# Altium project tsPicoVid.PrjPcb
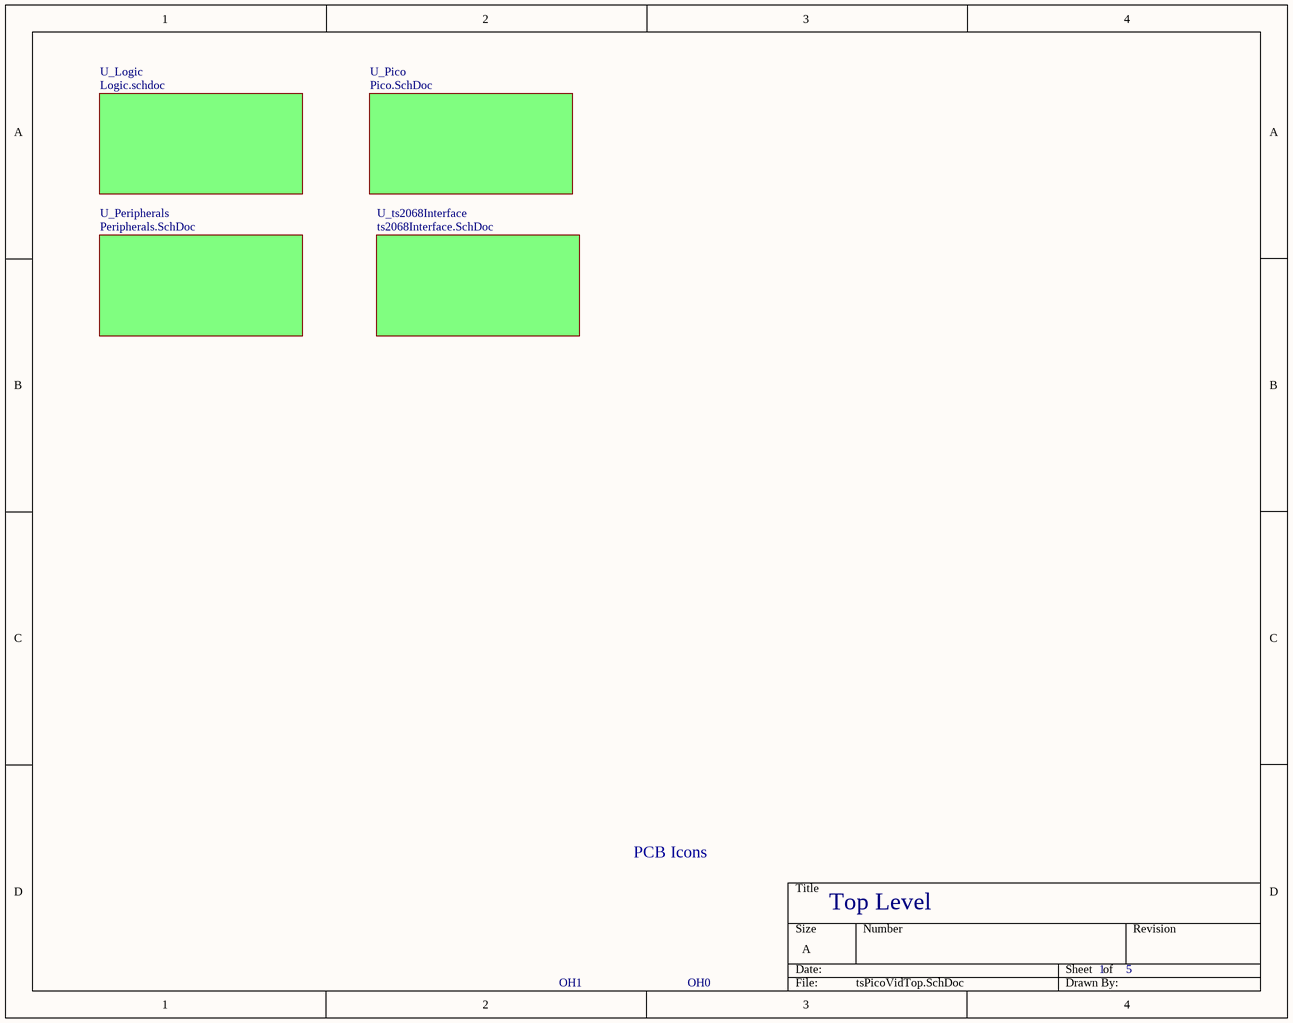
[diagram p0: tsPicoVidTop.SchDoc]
5 sheets, 47 parts. Net scope: global (net labels, ports and power ports of the same name join across sheets).
Sheets:
  tsPicoVidTop.SchDoc
    U_Logic = Logic.schdoc
    U_Pico = Pico.SchDoc
    U_ts2068Interface = ts2068Interface.SchDoc
    U_Peripherals = Peripherals.SchDoc

## Sheet tsPicoVidTop.SchDoc
size A; SheetNumber: 1; SheetTotal: 5

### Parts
OH0  OPENHW_PCB  [OpenHW]  (value not drawn)
OH1  OPENHW_SCH  (value not drawn)

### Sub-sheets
U_Logic = Logic.schdoc: no entries
U_Peripherals = Peripherals.SchDoc: no entries
U_Pico = Pico.SchDoc: no entries
U_ts2068Interface = ts2068Interface.SchDoc: no entries

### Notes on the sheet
- PCB Icons
- Top Level

## Sheet Logic.schdoc
size A; SheetNumber: 3; SheetTotal: 5
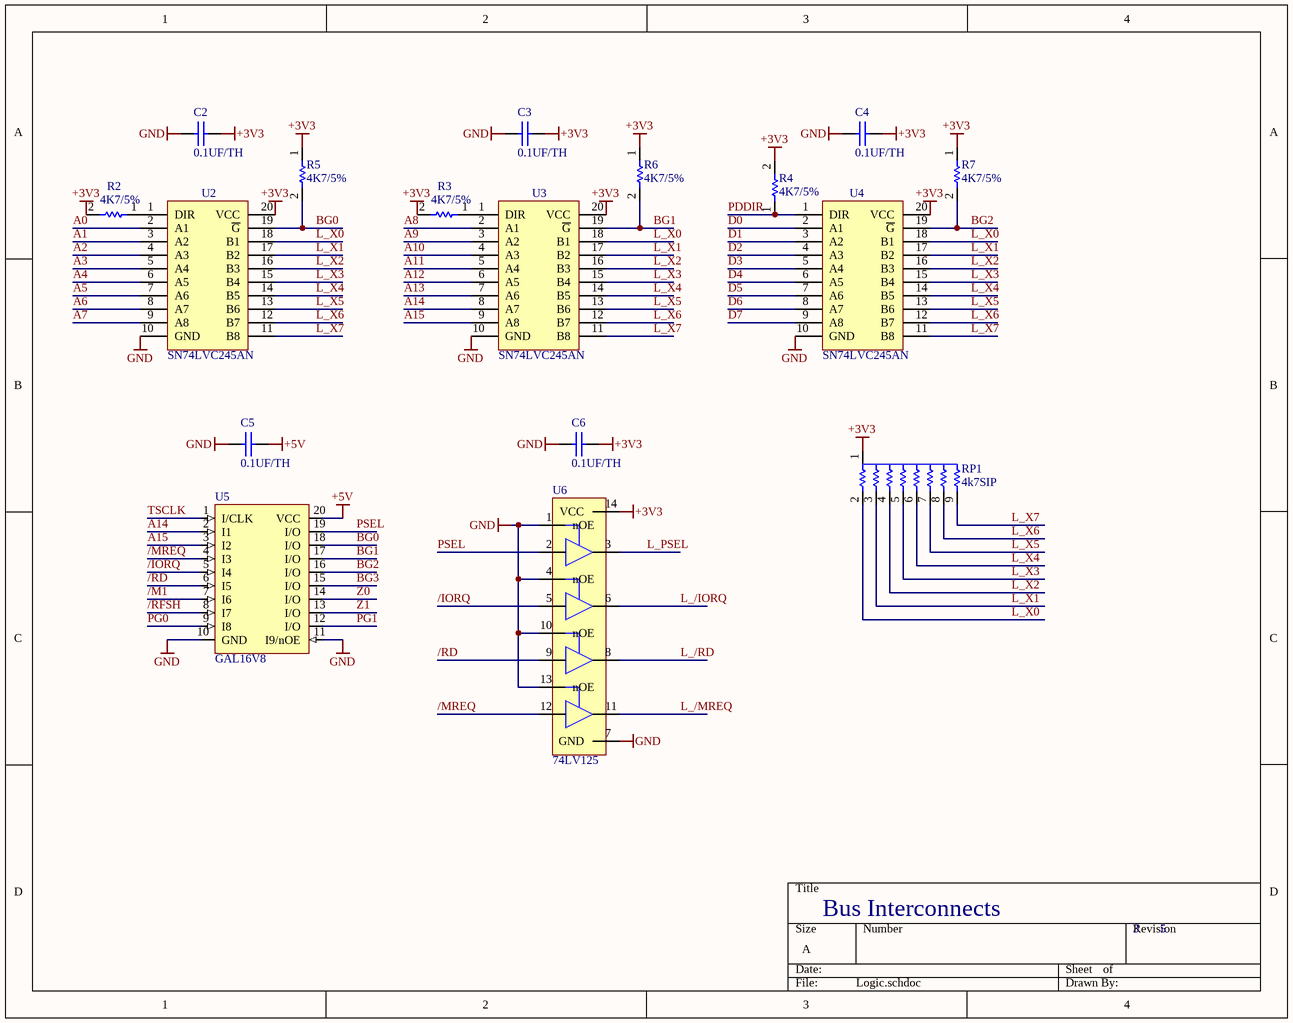
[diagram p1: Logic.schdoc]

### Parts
C2  0.1UF/TH  [CAPH5]
C3  0.1UF/TH  [CAPH5]
C4  0.1UF/TH  [CAPH5]
C5  0.1UF/TH  [CAPH5]
C6  0.1UF/TH  [CAPH5]
R2  4K7/5%  [CF18]
R3  4K7/5%  [CF18]
R4  4K7/5%  [CF18]
R5  4K7/5%  [CF18]
R6  4K7/5%  [CF18]
R7  4K7/5%  [CF18]
RP1  4k7SIP  [SIP9]
U2  SN74LVC245AN  [DIP20]
U3  SN74LVC245AN  [DIP20]
U4  SN74LVC245AN  [DIP20]
U5  GAL16V8  [DIP20]
U6  74LV125  [dip14]

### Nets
+3V3: C2.2 C3.2 C4.2 C6.2 R2.2 R3.2 R4.2 R5.1 R6.1 R7.1 RP1.1 U2.20(VCC) U3.20(VCC) U4.20(VCC) U6.14(VCC)
+5V: C5.2 U5.20(VCC)
GND: C2.1 C3.1 C4.1 C5.1 C6.1 U2.10(GND) U3.10(GND) U4.10(GND) U5.10(GND) U5.11(I9/nOE) U6.1(nOE) U6.4(nOE) U6.7(GND) U6.10(nOE) U6.13(nOE)
/IORQ: U5.5(I4) U6.5
/M1: U5.7(I6)
/MREQ: U5.4(I3) U6.12
/RD: U5.6(I5) U6.9
/RFSH: U5.8(I7)
A0: U2.2(A1)
A1: U2.3(A2)
A2: U2.4(A3)
A3: U2.5(A4)
A4: U2.6(A5)
A5: U2.7(A6)
A6: U2.8(A7)
A7: U2.9(A8)
A8: U3.2(A1)
A9: U3.3(A2)
A10: U3.4(A3)
A11: U3.5(A4)
A12: U3.6(A5)
A13: U3.7(A6)
A14: U3.8(A7) U5.2(I1)
A15: U3.9(A8) U5.3(I2)
BG0: R5.2 U2.19(~{G}) U5.18(I/O)
BG1: R6.2 U3.19(~{G}) U5.17(I/O)
BG2: R7.2 U4.19(~{G}) U5.16(I/O)
BG3: U5.15(I/O)
D0: U4.2(A1)
D1: U4.3(A2)
D2: U4.4(A3)
D3: U4.5(A4)
D4: U4.6(A5)
D5: U4.7(A6)
D6: U4.8(A7)
D7: U4.9(A8)
L_/IORQ: U6.6
L_/MREQ: U6.11
L_/RD: U6.8
L_PSEL: U6.3
L_X0: RP1.2 U2.18(B1) U3.18(B1) U4.18(B1)
L_X1: RP1.3 U2.17(B2) U3.17(B2) U4.17(B2)
L_X2: RP1.4 U2.16(B3) U3.16(B3) U4.16(B3)
L_X3: RP1.5 U2.15(B4) U3.15(B4) U4.15(B4)
L_X4: RP1.6 U2.14(B5) U3.14(B5) U4.14(B5)
L_X5: RP1.7 U2.13(B6) U3.13(B6) U4.13(B6)
L_X6: RP1.8 U2.12(B7) U3.12(B7) U4.12(B7)
L_X7: RP1.9 U2.11(B8) U3.11(B8) U4.11(B8)
PDDIR: R4.1 U4.1(DIR)
PG0: U5.9(I8)
PG1: U5.12(I/O)
PSEL: U5.19(I/O) U6.2
TSCLK: U5.1(I/CLK)
Z0: U5.14(I/O)
Z1: U5.13(I/O)
NetR2_1: R2.1 U2.1(DIR)
NetR3_1: R3.1 U3.1(DIR)

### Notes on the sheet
- Bus Interconnects

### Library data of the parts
C2-C6 = 0.1UF/TH: 0.1 µF ±10% 50V Ceramic Capacitor X7R Radial; MFG: Vishay; MFG PN: K104K10X7RF5UH5; DK PN: BC2665CT-ND
R2-R7 = 4K7/5%: RES 4.7K OHM 5% 1/8W AXIAL; MFG PN: CF18JT4K70; DK PN: CF18JT4K70CT-ND; MFG: Stackpole
RP1 = 4k7SIP: 4.7k Ohm ±2% 200mW Power Per Element Bussed Resistor Network/Array ±100ppm/°C 9-SIP; MFG: Bournes; MFG PN: 4609X-101-472LF; DK PN: 4609X-101-472LF-ND
U2-U4 = SN74LVC245AN: Transceiver, Non-Inverting 1 Element 8 Bit per Element 3-State Output 20-PDIP; MFG: TI; DK PN: 296-8503-5-ND
U5 = GAL16V8: GAL16V8 Programmable Logic Device (PLD) IC 8 Macrocells 20-PDIP; MFG: Microchip; MFG PN: ATF16V8C-7PU
U6 = 74LV125: Buffer, Non-Inverting 4 Element 1 Bit per Element 3-State Output 14-SOIC; MFG: TI; MFG PN: SN74LV125AN; DK PN: 296-34037-5-ND

## Sheet Pico.SchDoc: Mass Storage
size A; SheetNumber: 4; SheetTotal: 7
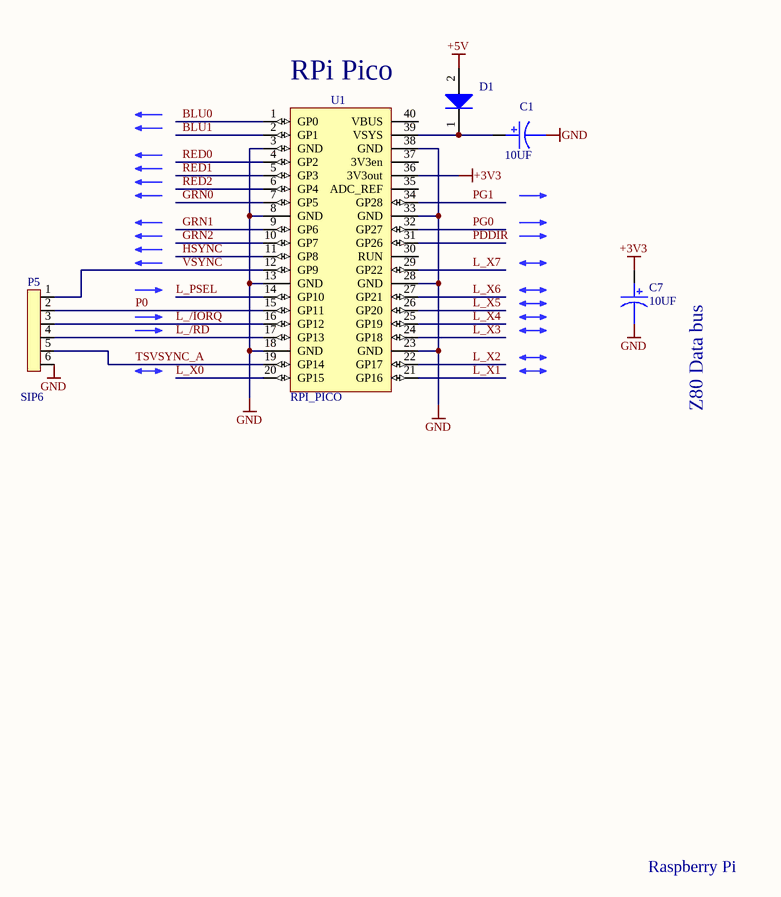
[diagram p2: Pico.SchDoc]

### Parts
C1  10UF  [CAP10EL]
C7  10UF  [CAP10EL]
D1  SB260_R2_00001  [DO-15]  (value not drawn)
P5  SIP6  [SIP6]
U1  RPI_PICO  [RPIPICO]

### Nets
+3V3: C7.1 U1.36(3V3out)
+5V: D1.2(A)
GND: C1.2 C7.2 P5.6 U1.3(GND) U1.8(GND) U1.13(GND) U1.18(GND) U1.23(GND) U1.28(GND) U1.33(GND) U1.38(GND)
BLU0: U1.1(GP0)
BLU1: U1.2(GP1)
GRN0: U1.7(GP5)
GRN1: U1.9(GP6)
GRN2: U1.10(GP7)
HSYNC: U1.11(GP8)
L_/IORQ: P5.3 U1.16(GP12)
L_/RD: P5.4 U1.17(GP13)
L_PSEL: U1.14(GP10)
L_X0: U1.20(GP15)
L_X1: U1.21(GP16)
L_X2: U1.22(GP17)
L_X3: U1.24(GP18)
L_X4: U1.25(GP19)
L_X5: U1.26(GP20)
L_X6: U1.27(GP21)
L_X7: U1.29(GP22)
P0: P5.2 U1.15(GP11)
PDDIR: U1.31(GP26)
PG0: U1.32(GP27)
PG1: U1.34(GP28)
RED0: U1.4(GP2)
RED1: U1.5(GP3)
RED2: U1.6(GP4)
TSVSYNC_A: P5.5 U1.19(GP14)
VSYNC: P5.1 U1.12(GP9)
NetC1_1: C1.1 D1.1 U1.39(VSYS)

Not connected (* = marked no-connect by the designer): U1 30(RUN) 35(ADC_REF) 37(3V3en) 40(VBUS)

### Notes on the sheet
- RPi Pico
- (near C7) Z80 Data bus
- Raspberry Pi

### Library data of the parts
C1 C7 = 10UF: CAP ALUM 10UF 20% 16V RADIAL; MFG: Panasonic; MFG PN: ECE-A1CKA100; DK PN: P807-ND
D1 = SB260_R2_00001: DIODE SCHOTTKY 60V 2A DO15; DK PN: 3757-SB260_R2_00001CT-ND; MFG: Panjit
U1 = RPI_PICO: RASPBERRY PI PICO RP2040 BOARD; MFG PN: SC0915; DK PN: 2648-SC0915CT-ND

## Sheet ts2068Interface.SchDoc
size A; SheetNumber: 2; SheetTotal: 5
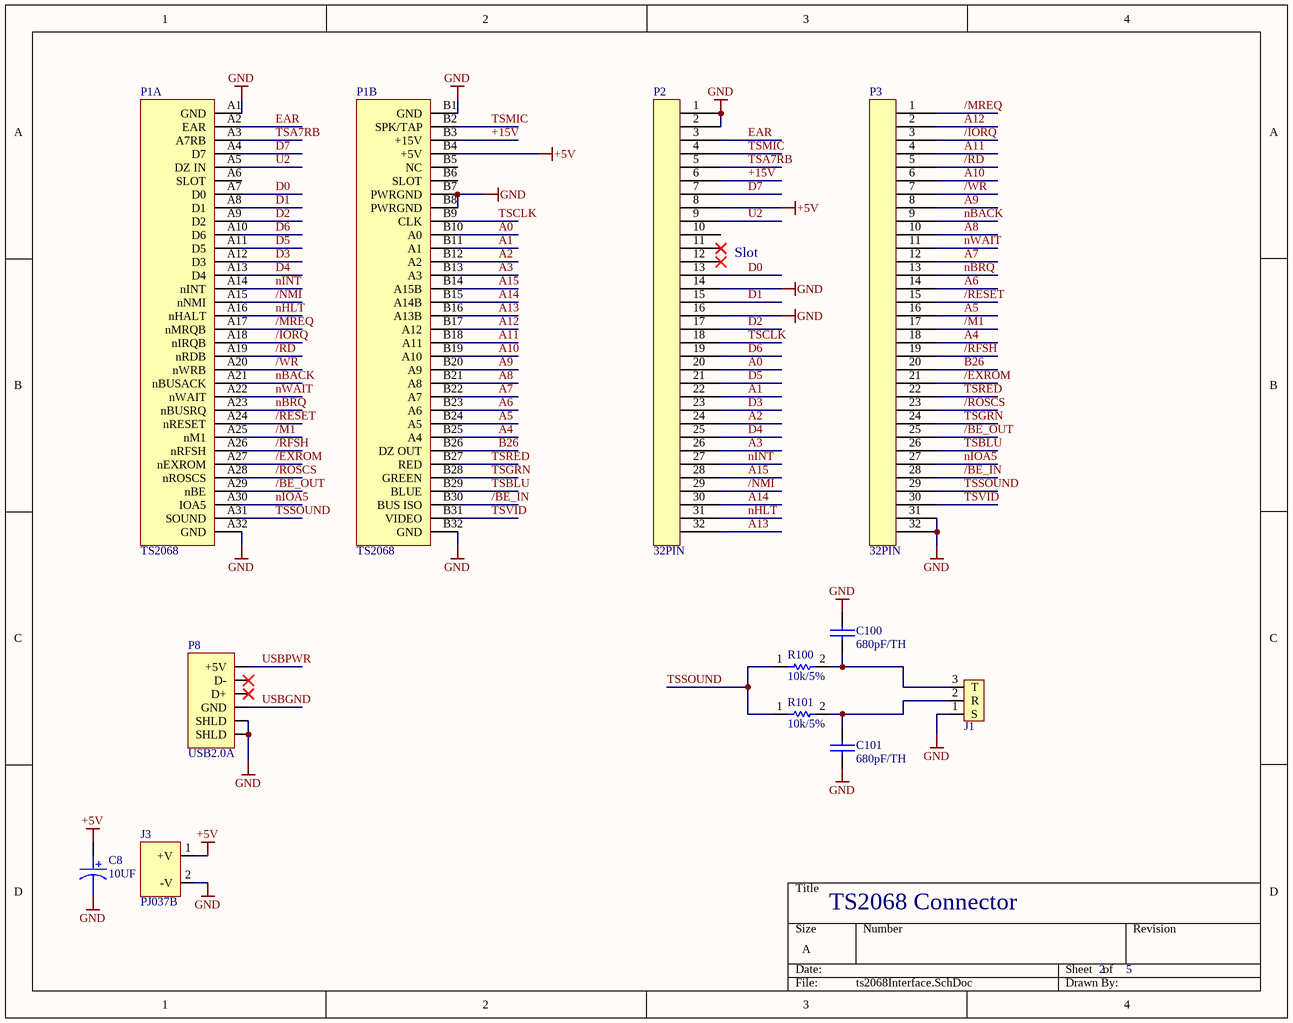
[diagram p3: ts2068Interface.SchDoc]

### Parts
C8  10UF  [CAP10EL]
C100  680pF/TH  [WIMIA_BOX2.7X4.5]
C101  680pF/TH  [WIMIA_BOX2.7X4.5]
J1  STX-3000  [STX-3000]  (value not drawn)
J3  PJ037B  [PJ037B]
P1  TS2068  [TS2068A]  (parts A,B of 2)
P2  32PIN  [IDC32]
P3  32PIN  [IDC32]
P8  USB2.0A  [USBA_AU-Y1005]
R100  10k/5%  [CF18]
R101  10k/5%  [CF18]

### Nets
+5V: C8.1 J3.1(+V) P1.B4(+5V) P2.8
GND: C8.2 C100.1 C101.2 J1.1(S) J3.2(-V) P1.A1(GND) P1.A32(GND) P1.B1(GND) P1.B7(PWRGND) P1.B8(PWRGND) P1.B32(GND) P2.1 P2.2 P2.14 P2.16 P3.31 P3.32 P8.5(SHLD) P8.6(SHLD)
+15V: P1.B3(+15V) P2.6
/BE_IN: P1.B30(BUS_ISO) P3.28
/BE_OUT: P1.A29(nBE) P3.25
/EXROM: P1.A27(nEXROM) P3.21
/IORQ: P1.A18(nIRQB) P3.3
/M1: P1.A25(nM1) P3.17
/MREQ: P1.A17(nMRQB) P3.1
/NMI: P1.A15(nNMI) P2.29
/RD: P1.A19(nRDB) P3.5
/RESET: P1.A24(nRESET) P3.15
/RFSH: P1.A26(nRFSH) P3.19
/ROSCS: P1.A28(nROSCS) P3.23
/WR: P1.A20(nWRB) P3.7
A0: P1.B10(A0) P2.20
A1: P1.B11(A1) P2.22
A2: P1.B12(A2) P2.24
A3: P1.B13(A3) P2.26
A4: P1.B25(A4) P3.18
A5: P1.B24(A5) P3.16
A6: P1.B23(A6) P3.14
A7: P1.B22(A7) P3.12
A8: P1.B21(A8) P3.10
A9: P1.B20(A9) P3.8
A10: P1.B19(A10) P3.6
A11: P1.B18(A11) P3.4
A12: P1.B17(A12) P3.2
A13: P1.B16(A13B) P2.32
A14: P1.B15(A14B) P2.30
A15: P1.B14(A15B) P2.28
B26: P1.B26(DZ_OUT) P3.20
D0: P1.A7(D0) P2.13
D1: P1.A8(D1) P2.15
D2: P1.A9(D2) P2.17
D3: P1.A12(D3) P2.23
D4: P1.A13(D4) P2.25
D5: P1.A11(D5) P2.21
D6: P1.A10(D6) P2.19
D7: P1.A4(D7) P2.7
EAR: P1.A2(EAR) P2.3
nBACK: P1.A21(nBUSACK) P3.9
nBRQ: P1.A23(nBUSRQ) P3.13
nHLT: P1.A16(nHALT) P2.31
nINT: P1.A14(nINT) P2.27
nIOA5: P1.A30(IOA5) P3.27
nWAIT: P1.A22(nWAIT) P3.11
TSA7RB: P1.A3(A7RB) P2.5
TSBLU: P1.B29(BLUE) P3.26
TSCLK: P1.B9(CLK) P2.18
TSGRN: P1.B28(GREEN) P3.24
TSMIC: P1.B2(SPK/TAP) P2.4
TSRED: P1.B27(RED) P3.22
TSSOUND: P1.A31(SOUND) P3.29 R100.1 R101.1
TSVID: P1.B31(VIDEO) P3.30
U2: P1.A5(DZ_IN) P2.9
USBGND: P8.4(GND)
USBPWR: P8.1(+5V)
NetC100_2: C100.2 J1.3(T) R100.2
NetC101_1: C101.1 J1.2(R) R101.2

Not connected (* = marked no-connect by the designer): P1 A6(SLOT) B5(NC) B6(SLOT); P2 10 11* 12*; P8 2(D-)* 3(D+)*

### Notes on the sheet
- Slot
- TS2068 Connector

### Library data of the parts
C8 = 10UF: as C1 on sheet Pico
C100 C101 = 680pF/TH: CAP FILM 680PF 10% 100VDC RAD; MFG: WIMA; MFG PN: FKP2D006801D00KSSD; DK PN: 1928-1238-ND
J1 = STX-3000: 3.50mm (0.141", 1/8", Mini Plug) - Headphone Phone Jack Stereo (3 Conductor, TRS) Connector Kinked Pin; DK PN: 2092-STX-3000-ND; MFG: Kycon, Inc.
J3 = PJ037B: Power Barrel Connector Jack 2.50mm ID (0.098"), 5.50mm OD (0.217") Through Hole, Right Angle; MFG PN: PJ-037B; DK PN: CP-037B-ND; MFG: CUI
P8 = USB2.0A: USB-A (USB TYPE-A) USB 2.0 Receptacle Connector 4 Position Through Hole, Right Angle; MFG: Adam Tech; MFG PN: USB-A-S-RA; DK PN: 2057-USB-A-S-RA-ND
R100 R101 = 10k/5%: RES 10K OHM 5% 1/8W AXIAL; MFG PN: CF18JT10K0; DK PN: CF18JT10K0CT-ND; MFG: Stackpole

## Sheet Peripherals.SchDoc
size A; SheetNumber: 4; SheetTotal: 5
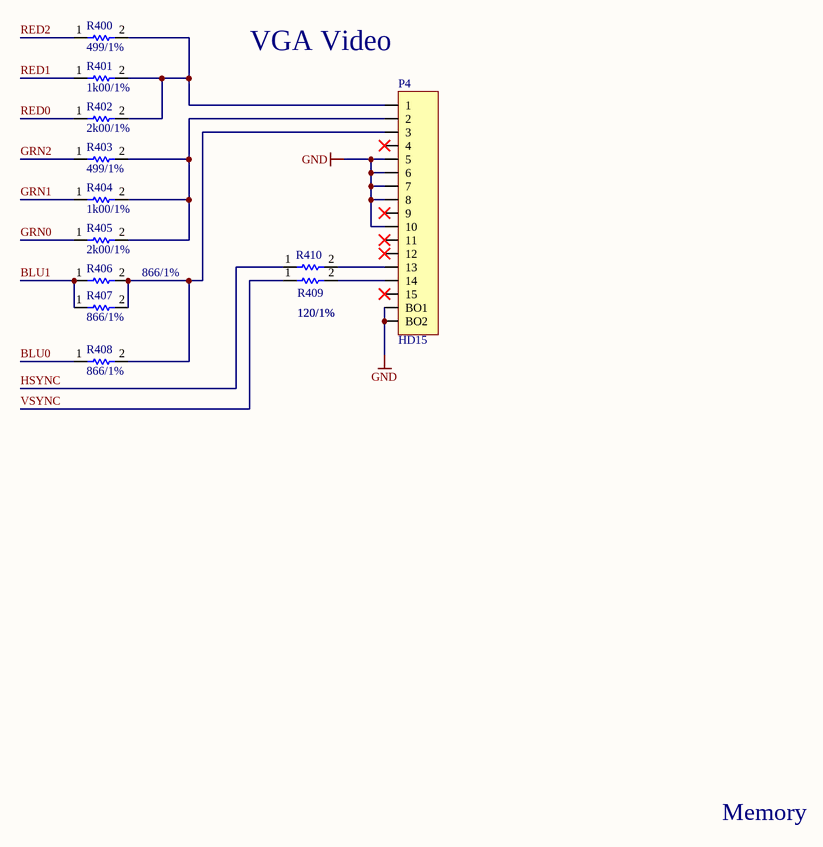
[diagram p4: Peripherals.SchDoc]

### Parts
P4  HD15  [DB15FLC]
R400  499/1%  [RNF14]
R401  1k00/1%  [RNF14]
R402  2k00/1%  [RNF14]
R403  499/1%  [RNF14]
R404  1k00/1%  [RNF14]
R405  2k00/1%  [RNF14]
R406  866/1%  [RNF14]
R407  866/1%  [RNF14]
R408  866/1%  [RNF14]
R409  120/1%  [RNF14]
R410  120/1%  [RNF14]

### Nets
GND: P4.5 P4.6 P4.7 P4.8 P4.10 P4.BO1 P4.BO2
BLU0: R408.1
BLU1: R406.1 R407.1
GRN0: R405.1
GRN1: R404.1
GRN2: R403.1
HSYNC: R410.1
RED0: R402.1
RED1: R401.1
RED2: R400.1
VSYNC: R409.1
NetP4_1: P4.1 R400.2 R401.2 R402.2
NetP4_2: P4.2 R403.2 R404.2 R405.2
NetP4_3: P4.3 R406.2 R407.2 R408.2
NetP4_13: P4.13 R410.2
NetP4_14: P4.14 R409.2

Not connected (* = marked no-connect by the designer): P4 4* 9* 11* 12* 15*

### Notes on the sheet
- (near P4) VGA Video
- Memory

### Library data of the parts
P4 = HD15: CONN DSUB HD RCPT 15POS R/A SLDR; Text Field1: Amphenol; Mfg PN: ICD15S13E4GX00LF; DK PN: 609-5181-ND
R400 R403 = 499/1%: RES 499 OHM 1% 1/4W AXIAL; MFG PN: RNF14FTD499R; DK PN: RNF14FTD499RCT-ND; MFG: Stackpole
R401 R404 = 1k00/1%: RES 1K OHM 1% 1/4W AXIAL; MFG PN: RNF14FTD1K00; DK PN: RNF14FTD1K00CT-ND; MFG: Stackpole
R402 R405 = 2k00/1%: RES 2K OHM 1% 1/4W AXIAL; MFG PN: RNF14FTD2K00; DK PN: RNF14FTD2K00CT-ND; MFG: Stackpole
R406-R408 = 866/1%: RES 866 OHM 1% 1/4W AXIAL; MFG PN: RNF14FTD866R; DK PN: RNF14FTD866RCT-ND; MFG: Stackpole
R409 R410 = 120/1%: RES 120 OHM 1% 1/4W AXIAL; MFG PN: RNMF14FTC120R; DK PN: S120CACT-ND; MFG: Stackpole

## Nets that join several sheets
+3V3: Logic (15 pins), Pico (C7.1 U1.36)
+5V: Logic (C5.2 U5.20), Pico (D1.2), ts2068Interface (C8.1 J3.1 P1.B4 P2.8)
GND: Logic (15 pins), Pico (11 pins), ts2068Interface (19 pins), Peripherals (7 pins)
/IORQ: Logic (U5.5 U6.5), ts2068Interface (P1.A18 P3.3)
/M1: Logic (U5.7), ts2068Interface (P1.A25 P3.17)
/MREQ: Logic (U5.4 U6.12), ts2068Interface (P1.A17 P3.1)
/RD: Logic (U5.6 U6.9), ts2068Interface (P1.A19 P3.5)
/RFSH: Logic (U5.8), ts2068Interface (P1.A26 P3.19)
A0: Logic (U2.2), ts2068Interface (P1.B10 P2.20)
A1: Logic (U2.3), ts2068Interface (P1.B11 P2.22)
A2: Logic (U2.4), ts2068Interface (P1.B12 P2.24)
A3: Logic (U2.5), ts2068Interface (P1.B13 P2.26)
A4: Logic (U2.6), ts2068Interface (P1.B25 P3.18)
A5: Logic (U2.7), ts2068Interface (P1.B24 P3.16)
A6: Logic (U2.8), ts2068Interface (P1.B23 P3.14)
A7: Logic (U2.9), ts2068Interface (P1.B22 P3.12)
A8: Logic (U3.2), ts2068Interface (P1.B21 P3.10)
A9: Logic (U3.3), ts2068Interface (P1.B20 P3.8)
A10: Logic (U3.4), ts2068Interface (P1.B19 P3.6)
A11: Logic (U3.5), ts2068Interface (P1.B18 P3.4)
A12: Logic (U3.6), ts2068Interface (P1.B17 P3.2)
A13: Logic (U3.7), ts2068Interface (P1.B16 P2.32)
A14: Logic (U3.8 U5.2), ts2068Interface (P1.B15 P2.30)
A15: Logic (U3.9 U5.3), ts2068Interface (P1.B14 P2.28)
BLU0: Pico (U1.1), Peripherals (R408.1)
BLU1: Pico (U1.2), Peripherals (R406.1 R407.1)
D0: Logic (U4.2), ts2068Interface (P1.A7 P2.13)
D1: Logic (U4.3), ts2068Interface (P1.A8 P2.15)
D2: Logic (U4.4), ts2068Interface (P1.A9 P2.17)
D3: Logic (U4.5), ts2068Interface (P1.A12 P2.23)
D4: Logic (U4.6), ts2068Interface (P1.A13 P2.25)
D5: Logic (U4.7), ts2068Interface (P1.A11 P2.21)
D6: Logic (U4.8), ts2068Interface (P1.A10 P2.19)
D7: Logic (U4.9), ts2068Interface (P1.A4 P2.7)
GRN0: Pico (U1.7), Peripherals (R405.1)
GRN1: Pico (U1.9), Peripherals (R404.1)
GRN2: Pico (U1.10), Peripherals (R403.1)
HSYNC: Pico (U1.11), Peripherals (R410.1)
L_/IORQ: Logic (U6.6), Pico (P5.3 U1.16)
L_/RD: Logic (U6.8), Pico (P5.4 U1.17)
L_PSEL: Logic (U6.3), Pico (U1.14)
L_X0: Logic (RP1.2 U2.18 U3.18 U4.18), Pico (U1.20)
L_X1: Logic (RP1.3 U2.17 U3.17 U4.17), Pico (U1.21)
L_X2: Logic (RP1.4 U2.16 U3.16 U4.16), Pico (U1.22)
L_X3: Logic (RP1.5 U2.15 U3.15 U4.15), Pico (U1.24)
L_X4: Logic (RP1.6 U2.14 U3.14 U4.14), Pico (U1.25)
L_X5: Logic (RP1.7 U2.13 U3.13 U4.13), Pico (U1.26)
L_X6: Logic (RP1.8 U2.12 U3.12 U4.12), Pico (U1.27)
L_X7: Logic (RP1.9 U2.11 U3.11 U4.11), Pico (U1.29)
PDDIR: Logic (R4.1 U4.1), Pico (U1.31)
PG0: Logic (U5.9), Pico (U1.32)
PG1: Logic (U5.12), Pico (U1.34)
RED0: Pico (U1.4), Peripherals (R402.1)
RED1: Pico (U1.5), Peripherals (R401.1)
RED2: Pico (U1.6), Peripherals (R400.1)
TSCLK: Logic (U5.1), ts2068Interface (P1.B9 P2.18)
VSYNC: Pico (P5.1 U1.12), Peripherals (R409.1)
